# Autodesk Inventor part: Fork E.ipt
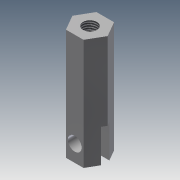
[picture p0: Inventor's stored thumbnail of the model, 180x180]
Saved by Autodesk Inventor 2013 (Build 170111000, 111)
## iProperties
Shininess: 64.0
Length Units: 11269
Angle Units: 11279
Time Units: 11290
Mass Units: 11283
Length Display Precision: 3
Angle Display Precision: 2
Compacted: True
Part Number: Fork E.ipt
Document SubType Name: Modeling
Created: 2005-02
Material: Steel, Mild
Designer: PVitaliy
Manufacturer: Standard
Standards Organization: Custom
Density: 7.86 g/cm^3
Mass: 25.2754 g
Surface Area: 22.752 cm^2
Volume: 3.2157 cm^3
Density: 0.0
Volumn: 0.0
Area: 0.0
PropertySet Name: Model Information
Control State: 0
Master: False
Checked Out: False
Checked Out Date: 2008-10-15
Last Check In Date: 2008-10-15
Author: PVitaliy
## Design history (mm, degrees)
sketch "Эскиз1"
  geometry: L1 (6.351, 0)-(3.175, -5.5); L2 (3.175, -5.5)-(-3.175, -5.5); L3 (-3.175, -5.5)-(-6.351, 0); L4 (-6.351, 0)-(-3.175, 5.5); L5 (-3.175, 5.5)-(3.175, 5.5); L6 (3.175, 5.5)-(6.351, 0); 1 further point
  constraints: 12 end point, 12 other
  dimensions: "d0" = 11 distance between parallel lines of L2 L5
extrude "Выдавливание1" new body sketch "Эскиз1" distance "d1" = 40; taper "d2" = 0 deg
sketch "Эскиз2"
  geometry: L1 (-3.175, -5.5)-(3.175, -5.5) reference; L2 (3.175, 5.5)-(-3.175, 5.5) reference; L3 (-6.351, 0)-(-3.175, -5.5) reference; L4 (3.175, -5.5)-(6.351, 0) reference; L5 (6.351, 0)-(3.175, 5.5) reference; L6 (-3.175, 5.5)-(-6.351, 0) reference; L7 (-8.891, 0)-(8.891, 0) reference; L8 (-5.485, -1.5)-(5.485, -1.5); L9 (-5.485, 1.5)-(5.485, 1.5)
  constraints: 4 end point, 4 point on line, 2 parallel
  dimensions: "d7" = 3 distance between parallel lines of L9 L8; "d8" = 1.5 distance between parallel lines of L7 L8
extrude "Выдавливание2" cut sketch "Эскиз2" distance "d5" = 12; taper "d6" = 0 deg
sketch "Эскиз4"
  geometry: C1 r 2.5 at (0, 0)
  constraints: 1 centre point, 1 other
  dimensions: "d9" = 5 diameter of C1
extrude "Выдавливание3" cut sketch "Эскиз4" distance "d10" = 20; taper "d11" = 0 deg
feature "Резьба1" dims "d12" = 10, "d13" = 0
sketch "Эскиз5"
  geometry: L1 (0, 0)-(6.351, 0) reference; L2 (0, 0)-(0, -40) reference; L3 (3.175, 0)-(3.175, -6)
  constraints: 2 end point, 1 midpoint, 1 parallel
  dimensions: "d14" = 6 distance of L3.start L3.end
hole "Отверстие1" sketch "Эскиз5" diameter "d15" = 5; stored, may be unused: countersink angle "d19" = 82 deg, drill point angle "d21" = 118 deg; dims "d16" = 6, "d17" = 4, "d18" = 2, "d20" = 8
body "Solid1"
